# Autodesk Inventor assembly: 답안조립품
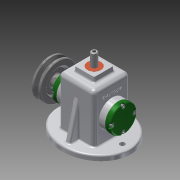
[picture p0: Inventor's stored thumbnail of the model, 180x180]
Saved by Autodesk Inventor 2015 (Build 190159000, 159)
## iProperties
Created: 2017-07
Part Number: 답안조립품
Document SubType Name: Assembly
Designer: Admin
Author: Admin
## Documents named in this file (16)
- C:\Users\Admin\Desktop\470707V1011\답안조립품.iam
- C:\Users\Admin\Desktop\470707V1011\본체.ipt
- C:\Users\Admin\Desktop\470707V1011\편심축.ipt
- C:\Users\Admin\Desktop\470707V1011\베어링 12 x 32 x 10.ipt
- C:\Users\Admin\Desktop\470707V1011\뒤커버.ipt
- C:\Users\Admin\Desktop\470707V1011\앞커버.ipt
- C:\Users\Admin\Desktop\470707V1011\오일실 12 25 7.ipt
- C:\Users\Admin\Desktop\470707V1011\볼트 M4 x 12.ipt
- C:\Users\Admin\Desktop\470707V1011\키 4 x 4 x 10.ipt
- C:\Users\Admin\Desktop\470707V1011\V벨트풀리.ipt
- C:\Users\Admin\Desktop\470707V1011\멈춤나사 M3x8.ipt
- C:\Users\Admin\Desktop\470707V1011\링크.ipt
- C:\Users\Admin\Desktop\470707V1011\핀 5 x 18.ipt
- C:\Users\Admin\Desktop\470707V1011\고정핀 1.2 x  8.ipt
- C:\Users\Admin\Desktop\470707V1011\슬라이드.ipt
- C:\Users\Admin\Desktop\470707V1011\부시.ipt
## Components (3 placed, 3 different names)
1. V벨트풀리:1 — 각도:3
2. 핀 5 x 18:1
3. 고정핀 1.2 x  8:1
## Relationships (1: Angle 1)
- 각도:3 [Angle]: V벨트풀리:1
